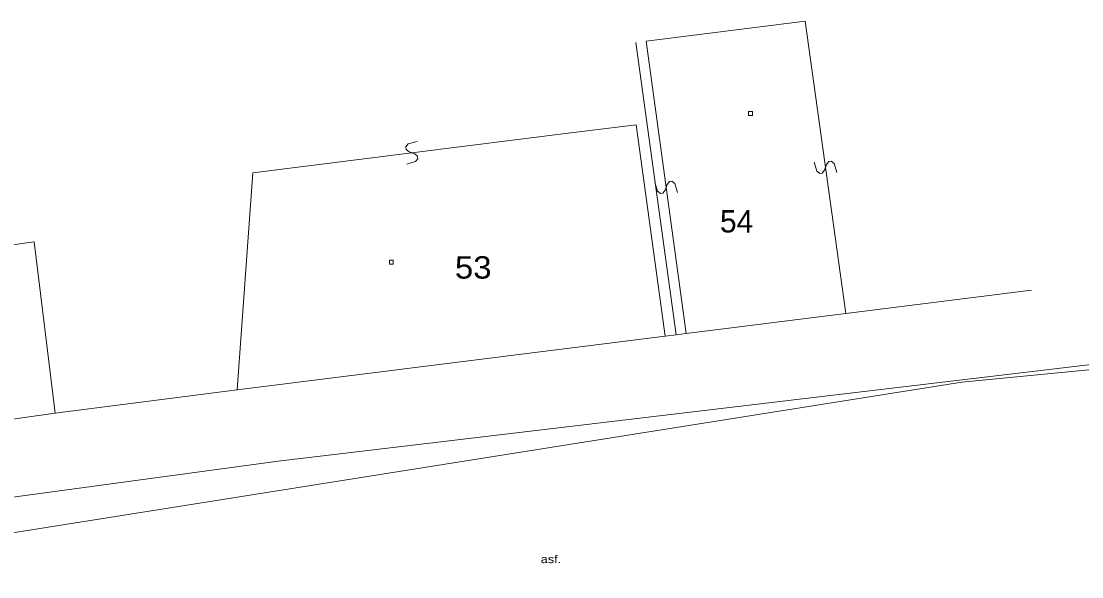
# Model space of a CAD drawing. Extents: x -736847 to -736508, y -1028413 to -1028271.
# Drawn here: x -736642.58 to -736602.28, y -1028292.02 to -1028270.93 of the extents above; entities that cross this region are included whole.
import ezdxf
from ezdxf.enums import TextEntityAlignment as Align

# ---------------------------------------------------------------- set-up
doc = ezdxf.new("R2010")
doc.units = 0
doc.header["$LTSCALE"] = 0.2
doc.layers.add('1', color=7, linetype='Continuous', lineweight=13)
doc.layers.add('2', color=7, linetype='Continuous', lineweight=13)
doc.layers.add('60', color=7, linetype='Continuous')

msp = doc.modelspace()

# ---------------------------------------------------------------- linework, layer by layer
at = {"layer": '1'}
for p, q in [((-736618.84, -1028271.69), (-736612.79, -1028270.93)), ((-736612.79, -1028270.93), (-736611.25, -1028282.02)), ((-736617.31, -1028282.78), (-736618.84, -1028271.69)), ((-736617.7, -1028282.83), (-736619.23, -1028271.74)), ((-736619.21, -1028274.86), (-736621.69, -1028275.17)), ((-736619.21, -1028274.86), (-736618.11, -1028282.88)), ((-736621.69, -1028275.17), (-736633.78, -1028276.68)), ((-736633.78, -1028276.68), (-736634.37, -1028284.92)), ((-736649.25, -1028280.31), (-736642.08, -1028279.3)), ((-736642.08, -1028279.3), (-736641.29, -1028285.81)), ((-736632.81, -1028287.63), (-736560.15, -1028279)), ((-736748.87, -1028303.31), (-736632.81, -1028287.63))]:
    msp.add_line(p, q, dxfattribs=at)
for points in [[(-736847.11, -1028304.1), (-736847.14, -1028305.98), (-736789.15, -1028305.56), (-736765.17, -1028304.89), (-736752.25, -1028304.39), (-736741.06, -1028303.76), (-736733.02, -1028303.04), (-736717.19, -1028301.44), (-736705.39, -1028300.01), (-736699.76, -1028298.26), (-736645.39, -1028290.74), (-736606.84, -1028284.63), (-736586.11, -1028282.62), (-736567.68, -1028281.15), (-736549.73, -1028280.36), (-736529.75, -1028279.79), (-736523.28, -1028279.48), (-736516.84, -1028278.77), (-736513.8, -1028278.17), (-736508.09, -1028276.55)], [(-736618.11, -1028282.88), (-736617.7, -1028282.83), (-736617.31, -1028282.78), (-736611.25, -1028282.02), (-736604.2, -1028281.14)], [(-736641.29, -1028285.81), (-736634.37, -1028284.92), (-736618.11, -1028282.88)], [(-736694.09, -1028293.26), (-736690.18, -1028292.72), (-736675.43, -1028290.55), (-736672.4, -1028290.07), (-736659.12, -1028288.32), (-736657.95, -1028288.15), (-736651.64, -1028287.22), (-736648.15, -1028286.77), (-736642.63, -1028286), (-736641.29, -1028285.81)]]:
    msp.add_lwpolyline(points, dxfattribs=at)
at = {"layer": '2'}
for points in [[(-736614.94, -1028274.36), (-736614.79, -1028274.36), (-736614.79, -1028274.51), (-736614.94, -1028274.51)], [(-736628.59, -1028280), (-736628.44, -1028280), (-736628.44, -1028280.15), (-736628.59, -1028280.15)]]:
    msp.add_lwpolyline(points, close=True, dxfattribs=at)
for points in [[(-736627.536, -1028275.497), (-736627.877, -1028275.59), (-736627.964, -1028275.701), (-736627.952, -1028275.8), (-736627.84, -1028275.887), (-736627.629, -1028275.962), (-736627.517, -1028276.049), (-736627.505, -1028276.148), (-736627.592, -1028276.259), (-736627.933, -1028276.352)], [(-736611.589, -1028276.667), (-736611.687, -1028276.327), (-736611.799, -1028276.242), (-736611.898, -1028276.256), (-736611.984, -1028276.369), (-736612.055, -1028276.58), (-736612.141, -1028276.693), (-736612.24, -1028276.707), (-736612.352, -1028276.622), (-736612.45, -1028276.282)], [(-736617.644, -1028277.427), (-736617.741, -1028277.088), (-736617.854, -1028277.002), (-736617.953, -1028277.016), (-736618.039, -1028277.129), (-736618.11, -1028277.34), (-736618.196, -1028277.453), (-736618.295, -1028277.467), (-736618.408, -1028277.381), (-736618.505, -1028277.042)]]:
    msp.add_lwpolyline(points, dxfattribs=at)

# ---------------------------------------------------------------- texts
msp.add_text('54', height=0.85, dxfattribs=at).set_placement((-736616.03, -1028278.95))
at = {"layer": '2', "width": 1.1}
msp.add_text('53', height=0.85, dxfattribs=at).set_placement((-736626.1, -1028280.7))
at = {"layer": '60', "width": 1.2}
msp.add_text('asf.', height=0.3, dxfattribs=at).set_placement((-736622.451, -1028291.5), align=Align.CENTER)

doc.saveas('drawing.dxf')
